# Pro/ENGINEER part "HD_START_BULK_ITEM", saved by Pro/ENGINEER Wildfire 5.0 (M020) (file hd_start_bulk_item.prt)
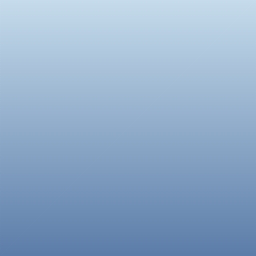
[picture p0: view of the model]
Units: Inch lbm Second (Pro/E Default); INCH, POUND, SECS

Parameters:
  MC_MODE = "BULK"
  MODEL_CHECK = "BULK"

Other parameters: MC_ERRORS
